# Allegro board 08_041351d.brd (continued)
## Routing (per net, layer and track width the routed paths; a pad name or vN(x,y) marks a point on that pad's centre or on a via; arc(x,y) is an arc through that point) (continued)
DDR3_DQ14: length 33
  TOP w0.197: U1.H1 v1(31.54,38.59)
  L12_SIGNAL w0.14: v1(48.83,18.77) 48.54,19.05 45.5,19.05 45.34,19.2 44.68,19.2 44.23,19.65 43.76,19.65 43.7,19.72 43.59,19.72 43.38,19.93 43.3,20 42.72,20 42.27,20.46 42.23,20.46 40.35,22.34 39.8,22.34 39.43,22.71 39.43,23.26 39.04,23.65 39.04,26.65 38.67,27.03 36.99,27.03 36.77,27.24 36.77,27.52 36.47,27.83 36.19,27.83 35.97,28.04 35.97,28.32 35.67,28.63 35.39,28.63 35.17,28.84 35.17,29.12 34.87,29.43 34.59,29.43 34.37,29.64 34.37,29.79 33.14,31.03 32.99,31.03 32.77,31.24 32.77,36.26 32.49,36.55 32.26,36.55 31.93,36.88 31.93,38.19 v1(31.54,38.59)
  BOTTOM w0.197: v1(48.83,18.77) U2.B8
DDR3_DQ15: length 33.1
  TOP w0.197: U1.J1 v1(30.74,38.59)
  L12_SIGNAL w0.14: v1(44.03,17.97) 44.03,17.41 43.74,17.13 41.84,17.13 37.14,21.83 36.63,21.83 36.23,22.23 36.19,22.23 35.9,22.52 35.9,24.39 35.66,24.63 35.39,24.63 35.17,24.84 35.17,25.12 34.86,25.43 34.59,25.43 34.37,25.64 34.37,25.92 34.06,26.23 33.79,26.23 33.57,26.44 33.57,26.72 33.26,27.03 32.99,27.03 32.77,27.24 32.77,27.52 32.46,27.83 32.19,27.83 31.97,28.04 31.97,28.32 31.66,28.63 31.39,28.63 31.17,28.84 31.17,29.12 30.86,29.43 30.59,29.43 30.37,29.64 30.37,30.13 30.03,30.48 30.03,30.59 29.9,30.72 29.64,30.72 29.52,30.84 29.52,38.02 29.64,38.15 30.01,38.15 30.45,38.59 v1(30.74,38.59)
  BOTTOM w0.197: U2.A3 v1(44.03,17.97)
DDR3_DQ16: length 30.3
  TOP w0.197: U1.P1 v1(25.94,38.59)
  L15_SIGNAL w0.14: v1(25.94,38.59) 25.94,39.83 26.21,40.11 30.28,40.11 30.66,40.49 39.55,40.49 39.93,40.88 41.45,40.88 41.71,40.62 41.71,40.24 41.58,40.11 39.65,40.11 39.42,39.89 39.42,39.57 39.65,39.35 41.45,39.35 41.58,39.22 41.58,38.97 41.45,38.84 40.44,38.84 40.31,38.72 40.31,38.21 40.53,37.99 41.98,37.99 42.28,38.29 42.58,38.29 42.87,37.99 v1(44.03,37.99)
  BOTTOM w0.197: U3.E3 44.09,37.99 v1(44.03,37.99)
DDR3_DQ17: length 30.2
  TOP w0.197: U1.P3 v1(25.94,36.99)
  L4_SIGNAL w0.14: v1(25.94,36.99) 25.94,37.04 26.34,37.45 26.34,39.61 26.99,40.25 28.11,40.25 28.37,39.99 30.91,39.99 31.93,38.97 35.1,38.97 35.24,39.11 35.24,39.59 35.38,39.73 35.66,39.73 35.8,39.59 35.8,39.11 35.94,38.97 36.22,38.97 36.36,39.11 36.36,39.73 36.49,39.86 36.79,39.86 36.92,39.73 36.92,39.11 37.06,38.97 39.8,38.97 41.33,37.45 44.25,37.45 44.5,37.7 46.93,37.7 v1(48.03,38.79)
  BOTTOM w0.197: U3.F7 47.96,38.79 v1(48.03,38.79)
DDR3_DQ18: length 30.4
  TOP w0.197: U1.R3 v1(25.14,36.99)
  L4_SIGNAL w0.14: v1(25.14,36.99) 25.14,37 25.57,37.44 25.57,39.85 26.34,40.62 28.12,40.62 28.37,40.88 28.37,43.29 28.63,43.54 30.28,43.54 30.53,43.29 30.53,40.88 30.79,40.62 32.62,40.62 32.76,40.48 32.76,40.13 32.9,39.99 33.18,39.99 33.32,40.13 33.32,40.48 33.46,40.62 33.73,40.62 33.87,40.48 33.87,40.13 34.01,39.99 34.29,39.99 34.43,40.13 34.43,40.48 34.57,40.62 39.04,40.62 41.07,38.59 42.06,38.59 42.28,38.37 42.58,38.37 42.8,38.59 43.09,38.59 v1(43.23,38.73)
  BOTTOM w0.197: U3.F2 v1(43.23,38.73)
DDR3_DQ19: length 30.3
  TOP w0.197: U1.R1 v1(25.14,38.59)
  L15_SIGNAL w0.14: v1(25.14,38.59) 25.14,40.3 25.71,40.88 39.17,40.88 39.55,41.26 41.84,41.26 42.09,41 42.09,40.5 42.06,40.48 42.06,39.37 42.34,39.09 44.25,39.09 45.78,40.62 47.17,40.62 47.42,40.37 47.42,40.2 v1(48.83,38.79)
  BOTTOM w0.197: U3.F8 48.76,38.79 v1(48.83,38.79)
DDR3_DQ20: length 30.3
  TOP w0.197: U1.T4 v1(24.34,36.19)
  L16_SIGNAL w0.14: v1(24.34,36.19) 23.9,36.63 22.89,36.63 22.6,36.63 22.3,36.32 22.3,35.29 22.56,35.03 24.56,35.03 24.77,35.24 24.77,35.54 24.99,35.75 25.28,35.75 25.57,36.04 25.57,37.94 25.86,38.23 26.09,38.23 26.37,38.52 26.37,38.74 26.59,38.95 26.7,38.95 27.74,39.99 30.28,39.99 30.79,40.49 40.57,40.49 40.82,40.75 43.61,40.75 v1(44.03,40.33)
  BOTTOM w0.197: U3.H3 v1(44.03,40.33)
DDR3_DQ21: length 30.4
  TOP w0.197: U1.U4 23.93,35.79 v1(23.53,36.19)
  L13_SIGNAL w0.14: v1(23.53,36.19) 23.93,36.59 23.93,38.59 23.97,38.63 23.97,38.74 26,40.76 26.36,40.76 26.37,40.77 28.12,40.77 28.34,40.99 30.42,40.99 30.63,40.77 36.47,40.77 36.5,40.75 39.68,40.75 40.31,40.11 42.13,40.11 42.28,39.97 44.18,39.97 44.32,40.11 45.9,40.11 46.15,39.86 48.19,39.86 48.66,40.33 v1(48.83,40.33)
  BOTTOM w0.197: U3.H8 v1(48.83,40.33)
DDR3_DQ22: length 30.3
  TOP w0.197: U1.U2 23.93,37.39 v1(23.53,37.79)
  L15_SIGNAL w0.14: v1(43.23,39.53) 42.85,39.9 42.85,41.13 42.34,41.64 39.3,41.64 38.91,41.26 22.79,41.26 20.63,39.1 20.63,38.35 20.75,38.23 20.99,38.23 21.01,38.21 23.11,38.21 v1(23.53,37.79)
  BOTTOM w0.197: U3.G2 v1(43.23,39.53)
DDR3_DQ23: length 30.3
  TOP w0.197: U1.U3 23.93,36.59 v1(23.53,36.99)
  L13_SIGNAL w0.14: v1(46.92,40.25) 46.55,40.62 44.76,40.62 44.12,41.26 30.03,41.26 29.91,41.38 26.6,41.38 26.48,41.26 23.42,41.26 22.79,40.62 22.79,39.35 23.17,38.97 23.17,37.35 v1(23.53,36.99)
  BOTTOM w0.197: U3.H7 47.15,40.25 v1(46.92,40.25)
DDR3_DQ24: length 30.5
  TOP w0.197: U1.V1 v1(22.74,38.59)
  L7_SIGNAL w0.14: v1(22.74,38.59) 23.12,38.97 23.55,38.97 24.07,39.49 25.47,39.49 25.49,39.5 28.17,39.5 28.19,39.49 34.89,39.49 35.03,39.63 35.03,39.97 35.17,40.11 35.44,40.11 35.58,39.97 35.58,39.63 35.72,39.49 36,39.49 36.14,39.63 36.14,39.97 36.28,40.11 36.56,40.11 36.7,39.97 36.7,39.63 36.84,39.49 38.77,39.49 38.78,39.48 40.44,39.48 41.96,37.95 41.96,37.82 43.08,36.7 43.34,36.7 43.36,36.68 43.87,36.68 43.88,36.69 45.78,36.69 46.79,37.7 47.52,37.7 v1(48.03,37.19)
  BOTTOM w0.197: v1(48.03,37.19) 47.96,37.19 U3.D7
DDR3_DQ25: length 30.5
  TOP w0.197: U1.Y3 v1(21.14,36.99)
  L13_SIGNAL w0.14: v1(44.03,36.33) 43.66,36.69 42.84,36.69 42.47,37.07 39.29,37.07 37.76,38.59 37.76,39.11 36.36,40.51 30.8,40.51 30.29,40 28.61,40 28.59,40.01 25.73,40.01 24.7,38.98 24.7,36.04 24.48,35.83 21.79,35.83 21.57,36.04 21.57,36.26 21.14,36.7 v1(21.14,36.99)
  BOTTOM w0.197: U3.C3 v1(44.03,36.33)
DDR3_DQ26: length 30.6
  TOP w0.197: U1.W1 v1(21.94,38.59)
  L7_SIGNAL w0.14: v1(48.83,36.27) 48.45,35.89 47.88,35.89 47.78,35.8 45.17,35.8 45.01,35.95 43.09,35.95 42.86,36.18 42.86,36.42 42.47,36.81 41.71,36.81 39.31,39.21 38.67,39.21 38.66,39.22 28.08,39.22 28.06,39.24 25.6,39.24 25.58,39.22 24.46,39.22 23.97,38.74 23.97,38.52 23.66,38.21 22.4,38.21 22.02,38.59 v1(21.94,38.59)
  BOTTOM w0.197: v1(48.83,36.27) 48.83,36.33 U3.C8
DDR3_DQ27: length 30.4
  TOP w0.197: U1.Y4 v1(21.14,36.19)
  L13_SIGNAL w0.14: v1(21.14,36.19) 21.14,35.9 21.57,35.46 21.57,35.24 21.79,35.03 25.32,35.03 25.57,35.28 25.57,38.97 26.35,39.75 28.48,39.75 28.5,39.73 30.53,39.73 31.04,40.24 35.99,40.24 37.28,38.95 37.29,38.95 37.5,38.74 37.5,38.48 39.3,36.68 41.45,36.68 42.22,35.92 42.82,35.92 v1(43.23,36.33)
  BOTTOM w0.197: U3.C2 v1(43.23,36.33)
DDR3_DQ28: length 30.5
  TOP w0.197: U1.Y2 v1(21.14,37.79)
  L15_SIGNAL w0.14: v1(48.03,34.73) 46.96,35.8 44.5,35.8 44.34,35.95 42.29,35.95 39.57,36.93 39.55,36.94 37.51,38.21 30.66,38.21 30.6,38.15 30.59,38.15 30.37,37.94 30.3,37.64 30.09,37.43 30.01,37.43 27.46,37.43 27.17,37.14 27.17,36.92 26.88,36.63 24.99,36.63 23.38,36.63 23.1,36.91 23.1,37.14 22.89,37.35 21.9,37.35 v1(21.14,37.79)
  BOTTOM w0.197: U3.A7 v1(48.03,34.73)
DDR3_DQ29: length 30.5
  TOP w0.197: U1.W3 v1(21.94,36.99)
  L15_SIGNAL w0.14: v1(43.23,34.67) 43.75,34.14 44.53,34.14 44.76,33.92 44.76,33.61 44.53,33.38 41.96,33.38 41.14,34.21 40.13,34.21 40.08,34.25 39.82,34.25 37.52,36.56 30.59,36.56 30.3,36.26 30.3,36.04 30.09,35.83 28.28,35.83 28.2,35.75 28.19,35.75 27.97,35.54 27.97,35.32 27.69,35.03 22.59,35.03 22.3,35.32 22.3,35.54 22.01,35.83 21.79,35.83 21.57,36.04 21.57,36.63 v1(21.94,36.99)
  BOTTOM w0.197: v1(43.23,34.67) 43.23,34.73 U3.A2
DDR3_DQ30: length 30.1
  TOP w0.197: U1.V2 v1(22.74,37.79)
  L15_SIGNAL w0.14: v1(48.83,35.53) 48.39,35.97 48.39,36.42 48.11,36.69 42.84,36.69 42.34,37.19 39.93,37.19 38.03,39.1 30.78,39.1 30.63,38.95 30.58,38.95 30.37,38.74 30.37,38.44 30.09,38.15 27.39,38.15 27.17,37.94 27.17,37.72 26.88,37.43 23.19,37.43 23,37.62 22.91,37.62 v1(22.74,37.79)
  BOTTOM w0.197: U3.B8 v1(48.83,35.53)
DDR3_DQ31: length 30.5
  TOP w0.197: U1.V3 v1(22.74,36.99)
  L15_SIGNAL w0.14: v1(44.03,34.67) 44.04,34.65 45.01,34.65 45.14,34.53 45.77,34.53 45.79,34.55 45.8,34.55 46.01,34.76 46.01,35.06 45.8,35.27 45.79,35.27 45.77,35.29 44.88,35.29 44.76,35.16 40.31,35.16 40.08,35.39 39.57,35.39 37.61,37.35 30.59,37.35 30.37,37.14 30.37,36.91 30.02,36.56 27.61,36.56 27.6,36.55 27.39,36.55 27.17,36.34 27.17,36.12 26.88,35.83 22.59,35.83 22.3,36.12 22.3,36.55 v1(22.74,36.99)
  BOTTOM w0.197: U3.A3 44.03,34.73 v1(44.03,34.67)
DDR3_DQS0_N: length 30.4
  TOP w0.152: v1(36.34,37.79) U1.B2
  L12_SIGNAL w0.13: v1(44.83,22.77) 44.8,22.77 44.63,22.59 44.63,22.33 44.5,22.21 44.35,22.21 44.25,22.31 44.25,24.47 43.72,25 42.09,25 41.45,25.64 41.45,29.95 39.3,32.11 39.3,33.89 39.04,34.14 38.15,34.14 37.9,33.89 37.9,30.91 37.39,30.4 36.99,30.4 36.61,30.78 36.56,30.78 36.47,30.88 36.47,30.97 36.6,31.1 36.63,31.1 36.76,31.22 36.76,37.32 36.34,37.74 v1(36.34,37.79)
  BOTTOM w0.152: U2.G3 v1(44.83,22.77)
DDR3_DQS0_P: length 30.4
  TOP w0.152: U1.C2 v1(35.54,37.79)
  L12_SIGNAL w0.13: v1(44.83,21.97) 44.81,21.95 44.25,21.95 43.99,22.21 43.99,24.37 43.62,24.74 41.98,24.74 41.2,25.53 41.2,29.85 39.04,32.01 39.04,33.78 38.93,33.89 38.26,33.89 38.15,33.78 38.15,30.8 37.5,30.14 36.88,30.14 36.5,30.53 36.45,30.53 35.98,31 35.98,37.35 v1(35.54,37.79)
  BOTTOM w0.152: U2.F3 v1(44.83,21.97)
DDR3_DQS1_N: length 32.8
  TOP w0.152: U1.F2 v1(33.14,37.79)
  L6_SIGNAL w0.13: v1(47.23,19.59) 47.4,19.42 47.4,19.24 47.06,18.9 46.92,18.9 46.79,19.03 46.53,19.03 46.41,18.9 43.59,18.9 43.37,19.12 42.94,19.12 42.9,19.16 41.71,19.16 40.54,20.32 40.54,20.56 40.18,20.91 39.95,20.91 37.9,22.97 37.9,29.05 37.75,29.2 37.75,29.24 37.46,29.53 37.46,29.61 37.49,29.64 37.49,29.94 37.28,30.14 36.99,30.14 36.96,30.12 36.87,30.12 36.59,30.4 36.54,30.4 36.35,30.59 34.32,30.59 34.09,30.82 34.09,30.97 34.34,31.22 34.34,35.57 34.08,35.83 33.79,35.83 33.53,36.08 33.53,38.08 33.41,38.21 33.23,38.21 33.14,38.12 v1(33.14,37.79)
  BOTTOM w0.152: U2.B7 47.23,19.57 v1(47.23,19.59)
DDR3_DQS1_P: length 32.8
  TOP w0.152: U1.G2 v1(32.34,37.79)
  L6_SIGNAL w0.13: v1(48.03,19.59) 47.68,19.24 47.68,19.16 47.17,18.65 43.61,18.65 43.37,18.41 42.28,18.41 42.07,18.62 42.07,18.79 41.96,18.9 41.6,18.9 40.29,20.22 40.29,20.45 40.08,20.66 39.85,20.66 37.64,22.86 37.64,23.07 37.64,28.94 37.49,29.09 37.49,29.14 37.28,29.34 37.24,29.34 37.15,29.43 36.99,29.43 36.78,29.64 36.78,29.8 36.69,29.89 36.69,29.94 36.48,30.14 36.44,30.14 36.25,30.33 34.22,30.33 33.83,30.72 33.83,30.97 33.58,31.22 33.58,35.68 33.42,35.83 32.99,35.83 32.78,36.04 32.78,37.35 v1(32.34,37.79)
  BOTTOM w0.152: U2.C7 48,19.59 v1(48.03,19.59)
DDR3_DQS2_N: length 30.5
  TOP w0.152: U1.T2 v1(24.34,37.79)
  L4_SIGNAL w0.13: v1(44.03,39.53) 43.73,39.53 43.37,39.89 42.28,39.89 42.07,39.68 41.38,39.68 39.8,41.26 31.45,41.26 31.19,41.51 31.19,44.03 30.66,44.56 28.12,44.56 27.71,44.15 27.71,41.62 27.51,41.41 27.36,41.26 25.6,41.26 24.18,39.84 24.18,38.97 23.93,38.72 23.93,38.21 24.34,37.8 v1(24.34,37.79)
  BOTTOM w0.152: U3.G3 v1(44.03,39.53)
DDR3_DQS2_P: length 30.5
  TOP w0.152: U1.R2 v1(25.14,37.79)
  L4_SIGNAL w0.13: v1(25.14,37.79) 25.1,37.83 24.82,37.83 24.69,37.95 24.69,38.74 24.44,38.99 24.44,39.73 25.71,41 27.46,41 27.61,41.15 27.97,41.51 27.97,44.05 28.23,44.3 30.55,44.3 30.94,43.92 30.94,41.41 31.34,41 39.69,41 41.28,39.42 41.77,39.42 42.01,39.17 43.92,39.17 43.99,39.1 43.99,38.76 v1(44.03,38.73)
  BOTTOM w0.152: U3.F3 v1(44.03,38.73)
DDR3_DQS3_N: length 30.3
  TOP w0.152: U1.W4 v1(21.94,36.19)
  L4_SIGNAL w0.13: v1(48.03,35.53) 48.03,35.67 47.77,35.92 47.68,35.92 47.42,35.67 47.17,35.67 46.92,35.92 46.79,35.92 46.28,35.41 43.74,35.41 43.5,35.17 42.28,35.17 42.04,35.41 41.58,35.41 40.31,36.68 38.15,36.68 37.26,35.8 29.77,35.8 29.65,35.92 28.88,35.92 28.76,35.8 24.06,35.8 23.88,35.62 23.88,35.24 23.68,35.03 23.38,35.03 23.17,35.25 23.17,35.6 22.97,35.8 22.28,35.8 21.94,36.14 v1(21.94,36.19)
  BOTTOM w0.152: U3.B7 v1(48.03,35.53)
DDR3_DQS3_P: length 30.3
  TOP w0.152: U1.W5 v1(21.94,35.39)
  L4_SIGNAL w0.13: v1(21.94,35.39) 21.94,35.68 21.58,36.04 21.58,36.34 21.79,36.54 22.14,36.54 22.15,36.56 28.5,36.56 28.88,36.18 29.39,36.18 29.77,36.56 37.66,36.56 38.05,36.94 40.42,36.94 41.69,35.67 42.06,35.67 42.28,35.89 42.43,35.89 42.53,35.98 43.07,35.98 43.08,35.97 43.49,35.97 43.79,35.67 46.17,35.67 46.68,36.18 47.94,36.18 v1(48.03,36.27)
  BOTTOM w0.152: U3.C7 48.03,36.33 v1(48.03,36.27)
DDR3_ODT: length 55.5
  TOP w0.197: U1.N5 v1(26.74,35.39) ; v1(42.43,42.73) 42.1,42.4 41.01,42.4 R162.1
  L12_SIGNAL w0.14: v1(42.43,42.73) 42.43,41.05 42.85,40.62 42.85,34.27 44.5,32.62 44.5,29.19 44.12,28.81 43.87,28.81 43.59,28.53 43.59,26.62 43.3,26.33 42.79,26.33 v1(42.43,25.97)
  L16_SIGNAL w0.14: v1(26.74,35.39) 26.75,35.39 27.11,35.03 28.75,35.03 29.14,35.41 29.14,37.7 29.64,38.21 39.8,38.21 41.58,36.43 41.58,33.89 43.61,31.86 43.61,28.18 43.38,27.94 43.08,27.94 43.08,27.94 42.58,27.94 42.58,27.94 42.2,27.94 41.68,28.46 41.48,28.46 41.33,28.3 41.33,27.88 42.43,26.78 v1(42.43,25.97)
  BOTTOM w0.197: U2.K1 v1(42.43,25.97) ; U3.K1 v1(42.43,42.73)
DDR3_RAS#: length 53
  TOP w0.197: v1(44.03,41.93) 44.37,42.27 45.33,42.27 R156.1 ; U1.P4 v1(25.94,36.19)
  L12_SIGNAL w0.14: v1(44.03,41.93) 45.26,40.69 45.26,29.56 45.4,29.42 45.63,29.42 45.77,29.28 45.77,29 45.63,28.86 45.4,28.86 45.26,28.72 45.26,28.44 45.4,28.3 45.63,28.3 45.77,28.16 45.77,27.88 45.63,27.74 45.4,27.74 45.26,27.6 45.26,25.64 44.83,25.2 v1(44.83,25.17)
  L16_SIGNAL w0.14: v1(44.83,25.17) 44.39,25.85 44.39,31.86 42.79,34.47 42.79,34.82 42.58,35.03 42.48,35.03 42.34,35.17 42.28,35.17 42.06,35.38 42.06,35.44 41.96,35.54 41.96,36.56 40.06,38.46 37.39,38.97 29.77,38.97 28.57,38.15 28.19,38.15 27.97,37.94 27.97,37.68 27.64,37.35 27.39,37.35 27.17,37.14 27.17,36.92 26.89,36.63 26.37,36.63 v1(25.94,36.19)
  BOTTOM w0.197: U3.J3 v1(44.03,41.93) ; U2.J3 v1(44.83,25.17)
DDR3_RST#: length 52.3
  TOP w0.197: v1(43.23,47.53) 43.41,47.53 43.99,48.11 43.99,48.37 43.85,48.51 43.56,48.51 R133.1 ; v1(36.34,36.19) U1.B4
  L12_SIGNAL w0.14: v1(43.23,30.77) 43.19,30.8 43.19,31.14 42.89,31.44 42.26,31.44 41.33,32.37 41.33,44.94 42.06,45.68 42.06,46.08 42.28,46.29 42.68,46.29 42.85,46.46 42.85,47.15 v1(43.23,47.53)
  L16_SIGNAL w0.14: v1(36.34,36.19) 35.98,36.54 35.69,36.54 35.69,36.55 29.78,36.55 29.52,36.81 29.52,37.19 29.75,37.43 37.29,37.43 37.43,37.57 39.93,37.57 40.95,36.56 40.95,34.14 40.82,34.02 40.44,34.02 40.31,33.89 40.31,32.33 40.44,32.2 40.82,32.2 40.95,32.33 40.95,33.26 41.07,33.38 41.58,33.38 41.71,33.26 41.71,32.28 v1(43.23,30.77)
  BOTTOM w0.197: v1(43.23,47.53) U3.T2 ; U2.T2 v1(43.23,30.77)
DDR3_WE#: length 51
  TOP w0.197: U1.M5 v1(27.54,35.39) ; v1(44.03,43.53) 44.29,43.8 45.33,43.8 R155.1
  L6_SIGNAL w0.14: v1(44.03,43.53) 44.03,43.32 43.61,42.91 43.61,35.92 44.31,35.22 44.82,35.22 44.95,35.1 44.95,34.59 46.03,33.51 46.03,27.97 v1(44.83,26.77)
  L7_SIGNAL w0.14: v1(27.54,35.39) 27.5,35.42 27.24,35.42 27.14,35.32 27.14,35.13 27.3,34.97 27.67,34.97 27.9,34.74 27.9,34.49 28.24,34.15 28.49,34.15 28.7,33.94 28.7,33.52 28.96,33.25 28.96,32.83 29.24,32.55 30.09,32.55 30.3,32.34 30.3,32.09 30.64,31.75 30.91,31.75 31.04,31.62 31.04,31.59 31.1,31.54 31.1,31.24 31.04,31.18 31.04,30.84 31.17,30.72 37.9,30.72 38.03,30.59 38.03,29.82 39.98,27.87 41,27.87 41.33,27.54 41.33,26.92 41.58,26.66 42.61,26.66 42.98,27.03 42.98,27.03 43.11,27.16 46.92,27.16 47.04,27.03 47.04,26.89 46.92,26.77 v1(44.83,26.77)
  BOTTOM w0.197: U3.L3 v1(44.03,43.53) ; U2.L3 v1(44.83,26.77)
DX_0_N: length 54.8
  TOP w0.089: U1.M10 v1(27.54,31.39)
  L4_SIGNAL w0.089: v1(70.28,48.93) 70.28,47.86 69.08,46.65 61.24,46.65 52.12,37.53 52.12,35.31 49.43,32.62 39.53,32.62 38.96,32.05 37.52,32.05 37.2,31.73 27.9,31.73 27.56,31.39 v1(27.54,31.39)
  BOTTOM w0.089: v1(70.28,48.93) 70.04,49.18 70.04,49.94 70.33,50.23 JX1.100
DX_0_P: length 54.8
  TOP w0.089: U1.M9 v1(27.54,32.19)
  L4_SIGNAL w0.089: v1(27.54,32.19) 27.54,32.47 27.66,32.6 37.23,32.6 37.52,32.3 38.85,32.3 39.42,32.87 49.33,32.87 51.87,35.41 51.87,37.64 61.14,46.91 68.97,46.91 70.03,47.97 70.03,48.62 69.91,48.74 69.77,48.74 v1(69.57,48.93)
  BOTTOM w0.089: JX1.98 69.53,50.23 69.82,49.94 69.82,49.18 v1(69.57,48.93)
ETH_MD1_N: length 30.1
  L12_SIGNAL w0.089: v1(16.31,11.92) 16.5,12.11 16.5,14.21 16.19,14.51 16.13,14.51 15.29,15.35 15.29,17.13 15.42,17.25 15.42,23.5 10.59,28.32 10.59,29.21 10.23,29.57 8.96,29.57 8.31,30.23 8.31,31.46 8.96,32.11 v1(9.58,32.11)
  BOTTOM w0.089: v1(16.31,11.92) 16.54,11.69 16.54,11.51 16.73,11.32 16.73,10.31 16.98,10.05 17.16,10.05 17.37,9.84 U10.27 ; JX3.53 8.88,32.17 9.2,31.86 9.32,31.86 v1(9.58,32.11)
ETH_MD1_P: length 30.1
  L12_SIGNAL w0.089: v1(9.58,31.48) 9.32,31.73 9.32,31.77 9.23,31.86 9.07,31.86 8.56,31.35 8.56,30.33 9.07,29.83 10.34,29.83 10.85,29.32 10.85,28.43 15.67,23.6 15.67,17.15 15.55,17.02 15.55,15.45 16.23,14.77 16.49,14.77 16.56,14.84 16.69,14.84 17.07,14.46 17.07,14.14 16.75,13.82 16.75,13.51 16.94,13.32 16.94,12.87 16.75,12.68 16.75,12.11 v1(16.94,11.92)
  BOTTOM w0.089: v1(9.58,31.48) 9.41,31.64 9.2,31.64 8.93,31.37 JX3.51 ; U10.28 17.4,10.34 17.32,10.27 17.07,10.27 16.94,10.4 16.94,11.41 16.75,11.6 16.75,11.73 v1(16.94,11.92)
ETH_MD2_N: length 30.7
  L6_SIGNAL w0.089: v1(14.02,32.11) 15.61,32.11 16.31,31.41 16.31,23.58 18.59,21.3 18.59,14.23 17.83,13.47 17.83,12.43 19.19,11.07 v1(19.19,10.14)
  BOTTOM w0.089: v1(14.02,32.11) 13.79,31.88 13.56,31.88 13.26,32.17 JX3.54 ; v1(19.19,10.14) 18.98,9.93 18.98,9.63 18.68,9.34 18.68,8.1 18.43,7.84 U10.23
ETH_MD2_P: length 30.7
  L6_SIGNAL w0.089: v1(18.47,10.14) 18.66,10.33 18.81,10.33 18.94,10.46 18.94,10.96 17.58,12.32 17.58,13.57 18.34,14.33 18.34,21.19 16.05,23.48 16.05,31.31 15.5,31.86 14.34,31.86 14.21,31.73 14.21,31.59 v1(14.02,31.4)
  BOTTOM w0.089: v1(14.02,31.4) 13.76,31.66 13.57,31.66 13.28,31.37 JX3.52 ; v1(18.47,10.14) 18.76,9.9 18.76,9.72 18.47,9.43 18.47,8.19 18.34,8.06 18.2,8.06 17.92,8.34 U10.24
ETH_MD3_N: length 42.9
  L12_SIGNAL w0.089: v1(16.31,8.49) 16.31,6.59 16.56,6.33 17.32,6.33 17.83,6.84 17.83,13.19 18.47,13.82 18.47,21.57 16.69,23.35 16.69,26.65 12.88,30.46 12.88,32.47 11.33,34.02 6.28,34.02 v1(6.02,34.27)
  BOTTOM w0.089: JP2.1 5.46,34.53 5.72,34.27 v1(6.02,34.27) ; U10.21 17.3,6.84 17.14,7 16.98,7 16.6,7.39 16.6,8.2 v1(16.31,8.49)
ETH_MD3_P: length 42.9
  L12_SIGNAL w0.089: v1(16.82,8.49) 16.56,8.24 16.56,7.86 16.82,7.6 16.82,7.35 16.56,7.09 16.56,6.69 16.67,6.59 17.22,6.59 17.58,6.94 17.58,13.29 18.21,13.93 18.21,21.47 16.44,23.24 16.44,26.55 12.63,30.36 12.63,32.37 11.23,33.76 7.93,33.76 7.67,33.51 7.42,33.51 7.16,33.76 7.04,33.76 6.78,33.51 6.66,33.51 6.4,33.76 6.15,33.76 5.89,33.51 5.89,33.38 6.02,33.26 v1(6.02,33)
  BOTTOM w0.089: v1(6.02,33) 5.64,33 5.46,32.82 JP1.1 ; U10.22 17.32,7.34 17.2,7.22 17.07,7.22 16.82,7.48 v1(16.82,8.49)
ETH_MD4_N: length 35.5
  L13_SIGNAL w0.089: v1(12.88,8.24) 13.07,8.43 13.07,32.41 13.54,32.87 14.15,32.87 14.68,32.34 15.02,32.34 15.11,32.44 15.11,32.6 v1(14.83,32.88)
  BOTTOM w0.089: JP4.1 14.84,32.87 v1(14.83,32.88) ; U10.17 17.27,4.84 17.14,4.97 16.47,4.97 16.35,5.1 13.71,5.1 13.13,5.68 13.13,7.99 v1(12.88,8.24)
ETH_MD4_P: length 35.5
  L13_SIGNAL w0.089: v1(14.78,30.72) 15.04,30.97 15.04,31.99 14.93,32.09 14.57,32.09 14.04,32.62 13.64,32.62 13.32,32.3 13.32,8.43 v1(13.51,8.24)
  BOTTOM w0.089: v1(13.51,8.24) 13.34,8.07 13.34,5.77 13.8,5.32 16.44,5.32 16.56,5.19 17.2,5.19 17.35,5.34 U10.18 ; JP3.1 15.42,30.72 v1(14.78,30.72)
ETH_PHY_LED0: length 21.7
  TOP w0.14: R18.2 v2(3.86,47.86)
  L16_SIGNAL w0.095: v2(3.86,47.86) 3.86,46.34 5.26,44.94 5.26,30.84 6.33,29.77 v1(6.84,29.77)
  BOTTOM w0.14: v1(6.84,29.77) JX3.47
ETH_PHY_LED1: length 46.7
  TOP w0.14: R17.2 v1(41.07,12.3)
  L4_SIGNAL w0.095: v1(41.07,12.3) 39.87,11.09 37.71,11.09 37.14,11.67 37.14,12.3 36.5,12.94 36.5,14.71 35.1,16.11 33.71,16.11 33.26,16.55 32.06,16.55 31.23,15.73 26.21,15.73 25.26,16.68 21.58,16.68 21.07,17.19 15.48,17.19 13.9,18.78 13.9,29.45 14.09,29.64 v1(14.09,30.02)
  BOTTOM w0.14: JX3.48 13.84,29.77 v1(14.09,30.02)
FB0: length 6.4
  TOP w0.14: U18.4 25.16,7.31 R29.2 24.44,9.38 22.79,9.38 21.86,10.31 R48.1
FB_1P8V: length 3.8
  TOP w0.14: v1(63.49,2.65) 63.82,2.98 U4.32
  BOTTOM w0.14: R45.1 R39.2 64.44,3.03 63.87,3.03 v1(63.49,2.65)
FB_1P35V: length 5.8
  TOP w0.305: R34.1 73.03,1.56 72.75,1.56 ; 72.75,1.56 71.12,1.56 69.7,2.98 U4.9 ; 72.75,1.56 R35.1
FPGA_DONE: length 33.7
  TOP w0.127: U1.R11 v1(25.14,29.79)
  TOP w0.14: R172.2 35.36,51.42 34.45,52.33 v1(33.58,52.33)
  L6_SIGNAL w0.095: v1(25.2,44.69) 25.2,41.26 24.8,40.85 24.8,30.23 25.14,29.89 v1(25.14,29.79)
  L7_SIGNAL w0.095: v1(25.2,44.69) 25.2,46.08 25.71,46.59 26.21,46.59 27.61,47.99 31.29,47.99 32.31,49 32.31,51.06 v1(33.58,52.33)
  BOTTOM w0.14: JX1.8 33.53,52.25 33.58,52.31 v1(33.58,52.33)
FPGA_VBATT: length 110.9
  TOP w0.127: v1(33.14,29.79) U1.F11
  TOP w0.14: R9.2 24.18,48.11 24.56,48.11 25.45,47.23 v1(26.09,47.23)
  L6_SIGNAL w0.102: v1(26.09,47.23) 24.69,48.62 24.69,49.64 24.44,49.89 24.44,52.43 22.5,54.37 22.5,56.97 23.48,57.96 29.45,57.96 30.02,58.53 33.2,58.53 33.53,58.2 v1(33.53,57.64) 34.47,57.64 35.1,58.27 43.64,58.27 45.67,60.31 55.66,60.31 57.08,58.88 71.2,58.88 78.29,51.79 78.29,43.67 v1(78.03,43.41)
  BOTTOM w0.102: v1(33.14,29.79) 33.14,29.89 32.69,30.33 30.79,30.33 30.28,30.84 30.28,35.65 30.08,35.85 29.79,35.85 29.59,36.05 29.59,36.48 29.14,36.94 29.14,38.72 28.5,39.35 26.34,39.35 25.45,40.24 25.45,43.92 25.58,44.05 25.58,46.08 26.09,46.59 v1(26.09,47.23)
  BOTTOM w0.14: JX1.7 v1(33.53,57.64)
  BOTTOM w0.254: U24.20 78.03,43.83 v1(78.03,43.41)
GPO0: length 42.9
  TOP w0.127: U17.B7 62,29.69 v1(62,29.69)
  L16_SIGNAL w0.095: v1(62,29.69) 64.49,29.69 65.69,30.89 69.57,30.89 70.28,31.6 70.28,36.94 75.36,42.02 75.36,43.54 74.73,44.18 74.73,46.46 79.43,51.16 80.49,51.16 81.09,50.57 v1(87.26,50.57)
  BOTTOM w0.14: JX4.1 v1(87.26,50.57)
GPO1: length 35.8
  TOP w0.127: U17.B6 v1(61.2,28.89)
  L16_SIGNAL w0.095: v1(61.2,28.89) U17.B6 64.75,29.29 65.54,30.08 69.58,30.08 70.73,31.22 70.73,36.87 77.78,43.92 77.78,48.29 v1(80.06,50.57)
  BOTTOM w0.14: JX4.2 v1(80.06,50.57)
GPO2: length 48
  TOP w0.127: U17.B5 v1(61.2,28.09)
  L16_SIGNAL w0.095: v1(87.3,49.77) 87.31,49.77 87.81,50.27 87.81,50.81 87.5,51.11 81.23,51.11 80.8,51.54 79.3,51.54 74.41,46.65 74.41,43.99 74.98,43.42 74.98,42.15 69.84,37 69.84,31.99 69.53,31.68 65.66,31.68 64.82,30.84 61.52,30.84 60.76,30.08 60.76,28.56 61.2,28.12 v1(61.2,28.09)
  BOTTOM w0.14: JX4.3 v1(87.3,49.77)
GPO3: length 37.5
  TOP w0.127: U17.B4 v1(61.2,27.29)
  L16_SIGNAL w0.095: v1(80.06,49.77) 80.06,48.88 79.68,48.5 78.67,48.5 78.41,48.24 78.41,42.65 75.68,39.92 75.68,36.18 74.82,35.32 73.74,35.32 71.93,33.51 71.93,31.73 69.9,29.7 65.71,29.7 64.52,28.51 62.56,28.51 62.38,28.33 62.38,27.95 62.13,27.69 61.57,27.69 61.2,27.32 v1(61.2,27.29)
  BOTTOM w0.14: JX4.4 80.06,49.77 v1(80.06,49.77)
INIT_B_0_JX2_09: length 51.4
  TOP w0.14: U1.R10 v1(25.14,31.39) ; v1(35.36,46.34) 35.61,46.59 R168.2
  L6_SIGNAL w0.095: v1(32.69,14.97) 32.31,15.35 32.31,16.87 31.29,17.89 31.29,18.78 30.53,19.54 30.53,21.22 30.44,21.32 30.41,21.32 29.52,22.21 29.52,26.44 28.97,26.98 26.53,26.98 26.32,27.2 26.32,30.21 v1(25.14,31.39) 25.14,31.41 25.58,31.86 25.58,44.3 v1(25.96,44.69)
  L7_SIGNAL w0.095: v1(35.36,46.34) 34.34,45.32 33.71,45.32 33.33,45.7 28.12,45.7 27.1,44.69 v1(25.96,44.69)
  BOTTOM w0.14: JX2.9 34.33,12.57 32.69,14.21 v1(32.69,14.97)
IO_00_34_AD9364_CLKSEL: length 97.1
  TOP w0.127: U1.R19 v1(25.14,23.39)
  TOP w0.14: Q6.1 84.61,55.57 84.48,55.44 v1(82.6,55.44)
  L3_SIGNAL w0.095: v1(76.51,49.89) 76.51,50.78 78.41,52.69 79.85,52.69 v1(82.6,55.44)
  L4_SIGNAL w0.095: v1(25.14,23.39) 25.16,23.39 25.47,23.07 25.47,22.5 26.72,21.25 36.37,21.25 38.98,18.65 v1(39.68,18.65)
  L16_SIGNAL w0.095: v1(39.68,18.65) 40.18,19.16 45.42,19.16 45.5,19.07 47.99,19.07 48.44,19.52 48.44,19.79 49.47,20.83 49.77,20.83 50.18,21.23 50.18,46.86 49.97,47.07 49.97,47.95 50.6,48.58 64.1,48.58 65.08,47.61 69.98,47.61 71.25,48.88 73.2,48.88 74.22,49.89 v1(76.51,49.89)
  BOTTOM w0.14: R54.1 75.74,50.65 v1(76.51,49.89)
IO_00_35_AD9364_RST: length 46.7
  TOP w0.127: U1.G14 v1(32.34,27.39) ; U17.K5 v1(68.4,28.09)
  L4_SIGNAL w0.095: v1(32.34,27.39) 31.93,26.98 31.93,23.22 32.18,22.97 38.79,22.97 39.23,23.41 41.71,23.41 41.96,23.16 53.12,23.16 53.13,23.17 53.22,23.17 53.71,23.67 64,23.67 64.89,24.56 64.89,25.44 65.27,25.83 65.27,28.11 65.71,28.55 68,28.55 68.4,28.16 v1(68.4,28.09)
IO_25_34_JX4: length 67.9
  TOP w0.127: U1.T19 v1(24.34,23.39)
  L3_SIGNAL w0.095: v1(24.34,23.39) 24.74,22.98 24.74,20.52 27.94,17.32 41.43,17.32 41.91,16.83 54.5,16.83 55.68,18.02 61.14,18.02 v1(61.65,18.52)
  BOTTOM w0.14: JX4.64 80,25.77 79.71,25.48 79.71,21.57 79.07,20.94 71.68,20.94 70.41,19.67 65.77,19.67 64.63,18.52 v1(61.65,18.52)
IO_25_35_AD9364_CLKOUT: length 53.6
  TOP w0.127: U17.J6 v1(67.6,28.89) ; U1.J15 v1(30.74,26.59)
  L7_SIGNAL w0.095: v1(30.74,26.59) 30.47,26.59 30.02,26.14 29.64,26.14 29.39,25.89 29.39,24.9 29.69,24.59 30.81,24.59 31.17,24.24 31.17,21.83 32.82,20.17 34.6,20.17 35.36,19.41 36.76,19.41 39.04,17.13 40.06,17.13 41.24,18.3 49.77,18.3 49.8,18.27 54.28,18.27 55.36,19.35 55.36,20.11 59.74,24.49 64.95,24.49 65.58,25.13 66.09,25.13 66.41,25.44 66.41,28.3 66.6,28.49 67.2,28.49 v1(67.6,28.89)
IO_L01_34_JX4_N: length 81.4
  TOP w0.089: U1.T10 v1(24.34,31.39)
  L4_SIGNAL w0.089: v1(24.34,31.39) 24.76,30.96 41.46,30.96 42.16,31.67 51.07,31.67 60.15,40.75 65.22,40.75 71.38,46.91 90.14,46.91 90.67,46.38 90.67,44.58 88.73,42.64 v1(87.81,42.64)
  BOTTOM w0.089: v1(87.81,42.64) 87.59,42.86 86.99,42.86 86.7,42.57 JX4.21
IO_L01_34_JX4_P: length 81.3
  TOP w0.089: U1.T11 v1(24.34,29.79)
  L4_SIGNAL w0.089: v1(87.81,43.35) 88.27,42.89 88.62,42.89 90.41,44.69 90.41,46.27 90.03,46.65 71.49,46.65 65.33,40.49 60.25,40.49 51.17,31.41 42.27,31.41 41.56,30.71 24.71,30.71 24.34,30.33 v1(24.34,29.79)
  BOTTOM w0.089: JX4.19 86.7,43.37 86.99,43.08 87.54,43.08 v1(87.81,43.35)
IO_L01_35_RX_D0_N: length 56.2
  TOP w0.089: U17.K11 v1(68.4,33.69) ; U1.B20 v1(36.34,22.59)
  L6_SIGNAL w0.089: v1(68.4,33.69) 68.79,34.09 68.79,35.31 67.67,36.43 58.31,36.43 57.98,36.09 57.59,36.09 55.55,34.05 55.55,28.47 51.04,23.96 51.04,18.59 48.76,16.3 41.12,16.3 39.91,17.51 36.99,17.51 36.32,18.17 36.32,19.93 35.87,20.39 35.87,20.86 36.34,21.33 v1(36.34,22.59)
IO_L01_35_RX_D0_P: length 56.2
  TOP w0.089: U17.J12 v1(67.6,34.49) ; U1.C20 v1(35.54,22.59)
  L6_SIGNAL w0.089: v1(35.54,22.59) 35.81,22.32 35.99,22.32 36.08,22.23 36.08,21.43 35.61,20.97 35.61,20.29 36.07,19.83 36.07,18.07 36.88,17.25 39.8,17.25 41.01,16.05 48.86,16.05 51.3,18.48 51.3,23.86 55.81,28.37 55.81,33.95 57.7,35.84 58.08,35.84 58.42,36.18 67.57,36.18 68.54,35.2 68.54,34.95 68.42,34.83 67.93,34.83 v1(67.6,34.49)
IO_L02_34_JX4_N: length 89.9
  TOP w0.089: U1.U12 v1(23.54,28.99)
  L15_SIGNAL w0.089: v1(80.04,42.6) 80.22,42.79 80.22,42.93 80.35,43.06 80.67,43.06 81.06,42.67 81.06,42.13 80.85,41.92 76.79,41.92 76.54,41.67 69.11,41.67 65.85,44.94 54.77,44.94 50.7,49 42.72,49 41.96,48.24 40.69,48.24 39.55,47.1 33.45,47.1 31.42,45.07 28.52,45.07 27.25,43.8 21.16,43.8 18.15,40.79 18.15,38.84 19.69,37.31 19.69,31.42 20.98,30.12 23,30.12 23.13,29.99 23.13,28.74 23.25,28.62 23.43,28.62 23.54,28.72 v1(23.54,28.99)
  BOTTOM w0.089: JX4.22 80.81,42.57 80.52,42.86 80.29,42.86 v1(80.04,42.6)
IO_L02_34_JX4_P: length 89.8
  TOP w0.089: U1.T12 v1(24.34,28.99)
  L15_SIGNAL w0.089: v1(24.34,28.99) 24.08,28.99 23.93,29.14 23.93,30.01 23.81,30.13 23.35,30.13 23.1,30.38 21.09,30.38 19.94,31.53 19.94,37.41 18.4,38.95 18.4,40.69 21.26,43.54 27.36,43.54 28.63,44.81 31.53,44.81 33.56,46.84 39.65,46.84 40.8,47.99 42.07,47.99 42.83,48.75 50.6,48.75 54.66,44.69 65.74,44.69 69.01,41.42 76.65,41.42 76.89,41.66 80.96,41.66 81.32,42.02 81.32,42.78 80.78,43.31 v1(80.04,43.31)
  BOTTOM w0.089: v1(80.04,43.31) 80.28,43.07 80.51,43.07 80.81,43.37 JX4.20
IO_L02_35_RX_D1_N: length 39.7
  TOP w0.089: U17.K10 v1(68.4,32.89) ; U1.A20 v1(37.14,22.59)
  L3_SIGNAL w0.089: v1(68.4,32.89) 68.4,32.62 68.27,32.49 67.39,32.49 67.17,32.28 67.17,30.27 66.92,30.02 66.39,30.02 64.76,28.39 64.76,27.98 64.51,27.73 60.24,27.73 59.98,27.98 55.24,27.98 51.77,24.52 44.41,24.52 43.63,25.29 42.45,25.29 40.62,23.47 37.59,23.47 37.47,23.35 37.47,23.25 37.27,23.05 36.98,23.05 36.89,22.96 36.89,22.84 v1(37.14,22.59)
IO_L02_35_RX_D1_P: length 39.8
  TOP w0.089: U17.J11 v1(67.6,33.69) ; v1(36.34,23.39) U1.B19
  L3_SIGNAL w0.089: v1(67.6,33.69) 67.87,33.69 68,33.57 68,33.39 67.87,33.26 67.36,33.26 67.17,33.07 67.17,32.68 66.98,32.49 66.66,32.49 66.35,32.18 66.35,30.33 64.57,28.56 60.29,28.56 59.97,28.24 55.13,28.24 51.67,24.77 44.52,24.77 43.74,25.55 42.34,25.55 40.52,23.72 37,23.72 36.76,23.48 36.76,23.23 36.71,23.18 36.54,23.18 v1(36.34,23.39)
IO_L03_34_JX4_N: length 114.5
  TOP w0.089: U1.V13 v1(22.74,28.19)
  L15_SIGNAL w0.089: v1(22.74,28.19) 23.05,28.19 23.18,28.06 23.18,27.89 23.07,27.78 22.62,27.78 22.34,27.5 22.34,27.16 22.15,26.97 20.88,26.97 20.63,26.71 20.18,26.71 19.48,27.41 15.86,27.41 13.58,29.7 13.58,35.92 14.72,37.07 14.72,39.22 14.02,39.92 14.02,44.39 18.06,48.43 27.65,48.43 30.51,51.29 72.59,51.29 74.62,49.26 78.03,49.26 79.05,48.24 80.44,48.24 82.09,46.59 84.63,46.59 86.2,45.03 86.2,41.38 86.89,40.68 87.26,40.68 87.35,40.6 88.06,40.6 88.18,40.48 88.18,40.3 88.1,40.23 v1(87.69,40.23)
  BOTTOM w0.089: v1(87.69,40.23) 87.45,40.46 86.99,40.46 86.7,40.17 JX4.27
IO_L03_34_JX4_P: length 115.1
  TOP w0.089: R53.1 v1(87.69,40.94) ; U1.U13 23.59,28.24 v1(23.54,28.19)
  L15_SIGNAL w0.089: v1(23.54,28.19) 23.54,27.87 23.17,27.5 23.17,27.2 22.94,26.97 22.51,26.97 22.37,26.83 22.37,26.4 22.18,26.21 20.88,26.21 20.63,26.46 20.08,26.46 19.38,27.16 15.76,27.16 13.32,29.59 13.32,36.03 14.47,37.17 14.47,39.12 13.77,39.82 13.77,44.5 17.96,48.69 27.55,48.69 30.41,51.54 72.7,51.54 74.73,49.51 78.14,49.51 79.15,48.5 80.55,48.5 82.2,46.84 84.74,46.84 86.45,45.13 86.45,41.49 87,40.94 v1(87.69,40.94)
  BOTTOM w0.089: v1(87.69,40.94) 87.43,40.68 87,40.68 86.71,40.97 JX4.25
IO_L03_35_RX_D2_N: length 44.5
  TOP w0.089: U1.D18 v1(34.74,24.19) ; U17.K9 v1(68.4,32.09)
  L7_SIGNAL w0.089: v1(34.74,24.19) 35.06,24.19 35.4,23.85 35.55,23.85 35.87,23.53 35.87,23.38 36.2,23.05 36.35,23.05 36.67,22.73 36.67,22.58 37,22.25 37.09,22.25 37.13,22.21 39.77,22.21 39.82,22.16 40.18,22.16 40.38,21.95 41.94,21.95 42.29,22.3 42.57,22.3 42.66,22.21 42.99,22.21 43.09,22.3 43.37,22.3 43.46,22.21 44.59,22.21 44.69,22.3 44.97,22.3 45.06,22.21 46.31,22.21 46.52,22 46.8,22 47.01,22.21 47.79,22.21 47.89,22.3 48.17,22.3 48.26,22.21 48.59,22.21 48.69,22.3 48.97,22.3 49.14,22.12 51.41,22.12 55.42,26.14 55.42,27.79 56.06,28.43 57.22,28.43 58.24,29.45 59.11,29.45 59.74,30.08 59.74,32.49 59.99,32.74 59.99,32.96 60.26,33.23 67.77,33.23 68,33 68,32.49 v1(68.4,32.09)
IO_L03_35_RX_D2_P: length 44.5
  TOP w0.089: U1.E17 v1(33.94,24.99) ; U17.J10 v1(67.6,32.89)
  L7_SIGNAL w0.089: v1(67.6,32.89) 67.62,32.87 67.62,32.62 67.49,32.49 66.6,32.49 66.54,32.56 65.84,32.56 65.42,32.98 64.89,32.98 64.73,32.82 64.73,32.75 64.54,32.56 60.17,32.56 60,32.39 60,29.98 59.21,29.19 58.35,29.19 57.33,28.18 56.16,28.18 55.68,27.69 55.68,26.04 51.51,21.87 49.21,21.87 48.91,21.57 42.34,21.57 42.22,21.7 40.28,21.7 40.07,21.91 39.71,21.91 39.67,21.95 37.03,21.95 36.98,22 36.89,22 36.66,22.23 36.21,22.23 35.87,22.58 35.87,22.73 35.55,23.05 35.4,23.05 35.07,23.38 35.07,23.53 34.75,23.85 34.6,23.85 34.28,24.17 34.28,24.81 34.1,24.99 v1(33.94,24.99)
IO_L04_34_JX4_N: length 98.7
  TOP w0.089: U1.W13 v1(21.94,28.19)
  L15_SIGNAL w0.089: v1(84.28,41.2) 84.28,42.28 83.72,42.83 82.48,42.83 80.62,44.69 78.23,44.69 76.96,43.42 75.34,43.42 72.8,45.96 69.56,45.96 67.15,48.37 52.76,48.37 50.92,50.21 41.54,50.21 39.06,47.73 30.85,47.73 29.14,46.02 27.59,46.02 26.95,46.65 23.61,46.65 21.52,44.56 19.31,44.56 17.07,42.31 17.07,36.05 16.63,35.61 16.63,30.67 18.17,29.13 20.37,29.13 20.92,28.58 21.54,28.58 v1(21.94,28.19)
  BOTTOM w0.089: v1(84.28,41.2) 84.28,40.47 83.98,40.17 JX4.28
IO_L04_34_JX4_P: length 98.7
  TOP w0.089: U1.V12 v1(22.74,28.99)
  L15_SIGNAL w0.089: v1(83.57,41.2) 83.76,41.39 83.9,41.39 84.02,41.51 84.02,42.17 83.62,42.58 82.37,42.58 80.52,44.43 78.34,44.43 77.07,43.16 75.24,43.16 72.7,45.7 69.46,45.7 67.04,48.11 52.65,48.11 50.81,49.96 41.64,49.96 39.17,47.48 30.96,47.48 29.24,45.76 27.48,45.76 26.85,46.4 23.72,46.4 21.62,44.3 19.42,44.3 17.32,42.21 17.32,35.94 16.88,35.5 16.88,30.78 18.28,29.38 22.34,29.38 v1(22.74,28.99)
  BOTTOM w0.089: JX4.26 82.67,40.97 82.76,40.88 82.76,40.51 82.88,40.39 83.89,40.39 84.06,40.56 84.06,40.84 83.92,40.98 83.78,40.98 v1(83.57,41.2)
IO_L04_35_RX_D3_N: length 43.9
  TOP w0.089: U17.K8 v1(68.4,31.29) ; U1.D20 v1(34.74,22.59)
  L3_SIGNAL w0.089: v1(34.74,22.59) 34.74,22.32 34.85,22.2 35.06,22.2 35.18,22.32 35.33,22.32 35.49,22.16 35.49,21.97 35.76,21.7 38.26,21.7 38.89,22.33 40.59,22.33 41.09,21.83 42.09,21.83 42.29,21.63 43.37,21.63 43.56,21.83 44.49,21.83 44.69,21.63 48.97,21.63 49.16,21.83 56.86,21.83 59.15,24.11 62.49,24.11 63.17,24.79 63.17,25.89 63.43,26.14 64.52,26.14 64.73,26.35 64.73,26.79 65.7,27.76 66.14,27.76 66.33,27.95 66.33,28.39 66.48,28.55 66.92,28.55 67.13,28.75 67.13,29.22 67.36,29.45 67.72,29.45 68.22,29.94 68.67,29.94 68.76,30.03 68.76,31.6 68.63,31.73 68.51,31.73 68.38,31.6 68.38,31.31 v1(68.4,31.29)
IO_L04_35_RX_D3_P: length 43.9
  TOP w0.089: U17.J9 v1(67.6,32.09) ; U1.D19 v1(34.74,23.39)
  L3_SIGNAL w0.089: v1(67.6,32.09) 68.06,31.63 68.06,30.14 67.62,29.7 66.85,29.7 66.33,29.18 66.33,28.75 66.14,28.56 65.71,28.56 65.33,28.18 65.33,27.75 64.41,26.83 62.66,26.83 62.41,26.58 62.41,24.62 62.16,24.37 59.04,24.37 56.76,22.08 49.2,22.08 48.98,22.3 47.89,22.3 47.51,21.93 45.25,21.93 45.16,22.02 45.16,22.1 44.97,22.3 42.29,22.3 42.06,22.08 41.2,22.08 40.69,22.59 38.79,22.59 38.15,21.95 35.87,21.95 35.74,22.08 35.74,22.26 35.94,22.46 35.94,22.78 35.75,22.97 35.16,22.97 v1(34.74,23.39)
IO_L05_34_JX4_N: length 91.3
  TOP w0.089: U1.T15 v1(24.34,26.59)
  L3_SIGNAL w0.089: v1(24.34,26.59) 24.34,26.89 24.27,26.95 24.1,26.95 23.94,26.79 23.94,22.38 23.7,22.14 23.7,17.44 25.16,15.98 31.8,15.98 32.11,16.29 55.48,16.29 56.63,17.44 61.95,17.44 62.23,17.73 62.23,18.73 62.68,19.18 63.29,19.18 63.41,19.31 63.41,19.44 v1(63.62,19.64)
  L13_SIGNAL w0.089: v1(83.49,38.61) 83.68,38.42 83.82,38.42 83.95,38.3 83.95,35.97 82.07,34.09 78.11,34.09 77.08,33.06 77.08,27.1 71.17,21.19 71.17,19.49 70.86,19.18 63.93,19.18 63.84,19.27 63.84,19.41 v1(63.62,19.64)
  BOTTOM w0.089: v1(83.49,38.61) 83.85,38.26 84.25,38.26 84.44,38.07 84.93,38.07 85.22,37.77 JX4.33
IO_L05_34_JX4_P: length 91.2
  TOP w0.089: U1.T14 v1(24.34,27.39)
  L3_SIGNAL w0.089: v1(63.62,18.93) 62.79,18.93 62.49,18.63 62.49,17.62 62.05,17.19 56.74,17.19 55.58,16.03 32.21,16.03 31.91,15.73 25.06,15.73 23.45,17.34 23.45,22.14 23.14,22.45 23.14,26.8 23.33,26.99 23.79,26.99 24.01,27.22 v1(24.34,27.39)
  L13_SIGNAL w0.089: v1(84.2,38.61) 84.2,35.87 82.17,33.84 78.21,33.84 77.33,32.96 77.33,26.99 71.43,21.09 71.43,19.39 70.97,18.93 v1(63.62,18.93)
  BOTTOM w0.089: JX4.31 85.19,38.57 84.9,38.28 84.53,38.28 v1(84.2,38.61)
IO_L05_35_RX_D4_N: length 41.2
  TOP w0.089: U1.E19 v1(33.94,23.39) ; U17.K7 v1(68.4,30.49)
  L4_SIGNAL w0.089: v1(68.4,30.49) 67.96,30.06 67.51,30.06 66.78,29.32 65.58,29.32 64.99,28.72 64.99,26.84 64.73,26.59 64.73,26.33 64.52,26.12 64.19,26.12 63.96,25.89 63.96,24.78 63.14,23.96 44.15,23.96 43.3,24.81 40.03,24.81 39.27,24.05 37.58,24.05 37.26,23.73 34.22,23.73 33.94,23.45 v1(33.94,23.39)
IO_L05_35_RX_D4_P: length 41.1
  TOP w0.089: U1.E18 v1(33.94,24.19) ; U17.J8 v1(67.6,31.29)
  L4_SIGNAL w0.089: v1(33.94,24.19) 33.94,24.21 34.34,24.62 37.26,24.62 37.58,24.3 39.16,24.3 39.93,25.06 43.4,25.06 44.25,24.21 63.03,24.21 63.25,24.43 63.25,25.82 63.46,26.03 63.61,26.03 64.03,26.46 64.03,26.65 64.21,26.83 64.44,26.83 64.73,27.12 64.73,28.83 65.48,29.57 66.67,29.57 67.26,30.16 67.26,30.96 v1(67.6,31.29)
IO_L06_13_JX2_P: length 59.2
  TOP w0.127: U1.V5 v1(22.74,35.39)
  L4_SIGNAL w0.095: v1(38.03,9.51) 38.03,9.7 36.25,11.47 36.25,13.06 35.29,14.01 35.29,15.35 34.79,15.86 33.45,15.86 33.07,16.24 32.12,16.24 31.29,15.41 26.09,15.41 25.2,16.3 17.58,16.3 17.39,16.49 15.48,16.49 13.51,18.46 13.51,33 15.55,35.03 22.4,35.03 22.74,35.36 v1(22.74,35.39)
  BOTTOM w0.14: v1(38.03,9.51) 37.53,9.01 JX2.18
IO_L06_34_JX4_N: length 80.2
  TOP w0.089: U1.R14 v1(25.14,27.39)
  L3_SIGNAL w0.089: v1(25.14,27.39) 25.14,27.35 24.74,26.96 24.74,23.98 24.93,23.79 25.34,23.79 25.54,23.6 25.54,21.12 26.44,20.22 27.98,20.22 29.12,19.08 40.3,19.08 42.09,17.29 50.64,17.29 51.62,18.27 54.89,18.27 55.71,19.08 58.91,19.08 60.38,20.56 62.84,20.56 v1(63.04,20.35)
  L13_SIGNAL w0.089: v1(63.04,20.35) 63.25,20.56 65.08,20.56 66.28,21.76 70.52,21.76 71.3,22.55 71.3,25.91 72.23,26.84 74.14,26.84 75.74,28.45 75.74,35.29 78.07,37.62 78.25,37.62 v1(78.45,37.42)
  BOTTOM w0.089: JX4.34 80.79,37.77 80.5,38.06 79.54,38.06 79.12,37.65 78.69,37.65 v1(78.45,37.42)
IO_L06_34_JX4_P: length 80.2
  TOP w0.089: U1.P14 v1(25.94,27.39)
  L3_SIGNAL w0.089: v1(25.94,27.39) 25.54,26.99 25.54,23.98 25.71,23.81 26.14,23.81 26.34,23.61 26.34,22.33 26.19,22.18 25.93,22.18 25.8,22.04 25.8,21.23 26.55,20.47 28.09,20.47 29.22,19.34 40.4,19.34 42.19,17.55 50.53,17.55 51.51,18.52 54.79,18.52 55.6,19.34 58.8,19.34 60.28,20.81 62.79,20.81 v1(63.04,21.06)
  L13_SIGNAL w0.089: v1(78.45,38.13) 78.19,37.87 77.97,37.87 75.49,35.39 75.49,28.56 74.03,27.1 72.12,27.1 71.05,26.02 71.05,22.65 70.41,22.02 66.18,22.02 64.97,20.81 63.3,20.81 v1(63.04,21.06)
  BOTTOM w0.089: v1(78.45,38.13) 78.71,37.87 79.03,37.87 79.45,38.28 80.51,38.28 80.81,38.57 JX4.32
IO_L06_35_RX_D5_N: length 46.3
  TOP w0.089: v1(33.14,24.99) U1.F17 ; U17.J7 v1(67.6,30.49)
  L7_SIGNAL w0.089: v1(67.6,30.49) 67.18,30.08 65.82,30.08 65.56,29.83 63.28,29.83 63.02,29.57 62.35,29.57 62.14,29.36 61.86,29.36 61.64,29.57 60.48,29.57 57.96,27.05 57.96,25.02 54.77,21.83 53.27,21.83 51.61,20.17 50.15,20.17 50,20.03 47.89,20.03 47.74,20.17 45.14,20.17 44.99,20.03 43.09,20.03 42.94,20.17 42.19,20.17 41.56,19.54 39.55,19.54 38.03,21.06 36.37,21.06 35.87,21.57 33.6,21.57 32.8,22.37 32.8,24.51 32.69,24.62 32.69,24.87 32.82,25 33.12,25 v1(33.14,24.99)
IO_L06_35_RX_D5_P: length 46.2
  TOP w0.089: v1(33.14,25.79) U1.F16 ; U17.H8 v1(66.8,31.29)
  L7_SIGNAL w0.089: v1(66.8,31.29) 66.41,30.91 65.89,30.91 65.65,30.67 65.65,30.27 65.46,30.08 63.17,30.08 62.92,29.83 62.34,29.83 62.14,30.03 61.86,30.03 61.65,29.83 60.38,29.83 57.71,27.16 57.71,25.13 54.66,22.08 53.16,22.08 51.51,20.43 50.09,20.43 49.82,20.7 47.89,20.7 47.61,20.43 45.26,20.43 44.99,20.7 43.09,20.7 42.81,20.43 42.09,20.43 41.45,19.79 39.65,19.79 38.13,21.32 36.48,21.32 35.97,21.83 33.71,21.83 33.45,22.08 33.45,22.33 33.58,22.46 33.58,25.38 33.17,25.79 v1(33.14,25.79)
IO_L07_34_JX4_N: length 131.8
  TOP w0.089: U1.Y17 21.54,25.38 21.14,24.99 v1(21.14,24.99)
  L15_SIGNAL w0.089: v1(90.78,39.68) 91.37,40.27 91.37,45.96 90.35,46.97 90.35,49.51 84.82,55.04 41.64,55.04 40.63,54.02 40.63,52.75 40.12,52.24 34.89,52.24 34,53.13 30.66,53.13 27.87,50.34 25.62,50.34 24.67,51.29 16.75,51.29 12.56,47.1 12.56,29.25 16.18,25.64 19.5,25.64 20.14,24.99 v1(21.14,24.99)
  BOTTOM w0.089: JX4.37 86.74,36.17 87.03,36.46 88.72,36.46 89.61,37.36 89.61,38.52 v1(90.78,39.68)
IO_L07_34_JX4_P: length 131.9
  TOP w0.089: U1.Y16 v1(21.14,25.79)
  L15_SIGNAL w0.089: v1(21.14,25.79) 21.45,25.79 21.55,25.69 21.55,25.51 21.44,25.39 20.93,25.39 20.78,25.24 20.25,25.24 19.6,25.89 16.29,25.89 12.82,29.36 12.82,46.99 16.86,51.04 24.56,51.04 25.52,50.08 27.97,50.08 30.76,52.88 33.9,52.88 34.79,51.99 40.23,51.99 40.88,52.64 40.88,53.91 41.75,54.78 84.72,54.78 90.1,49.41 90.1,46.87 91.11,45.85 91.11,40.38 90.83,40.1 90.66,40.1 90.57,40.19 v1(90.28,40.19)
  BOTTOM w0.089: v1(90.28,40.19) 90.28,39.9 90.39,39.78 90.39,39.6 89.4,38.61 89.4,37.45 88.63,36.68 87.04,36.68 86.75,36.97 JX4.35
IO_L07_35_RX_FRAME_N: length 71.1
  TOP w0.089: U1.M20 v1(27.54,22.59) ; U17.G7 v1(66,30.49)
  L12_SIGNAL w0.089: v1(66,30.49) 65.97,30.46 65.71,30.46 65.58,30.33 65.58,29.95 65.71,29.83 66.22,29.83 66.82,29.23 67.03,29.23 70.14,29.23 70.33,29.03 70.33,29.01 71.68,27.67 71.68,20.8 70.72,19.84 68.4,19.84 65.93,17.38 57.3,17.38 54.97,15.04 52.86,15.04 52.27,14.46 43.25,14.46 41.73,12.94 37.75,12.94 37.56,13.12 37.56,14.52 36.73,15.35 35.97,15.35 34.91,16.41 34.71,16.41 34.51,16.61 34.51,16.81 33.43,17.89 30.79,17.89 28.12,20.56 28.12,20.91 27.45,21.58 27.45,22.05 27.61,22.21 27.74,22.21 27.99,22.46 27.99,22.72 28.12,22.85 28.12,23.1 27.99,23.22 27.87,23.22 27.48,22.84 27.48,22.64 v1(27.54,22.59)
IO_L07_35_RX_FRAME_P: length 71.1
  TOP w0.089: U17.G8 v1(66,31.29) ; U1.M19 v1(27.54,23.39)
  L12_SIGNAL w0.089: v1(27.54,23.39) 27.52,23.39 27.2,23.06 27.2,21.48 27.87,20.81 27.87,20.45 30.68,17.63 33.33,17.63 34.26,16.7 34.26,16.5 34.61,16.16 34.81,16.16 35.87,15.09 36.63,15.09 37.31,14.41 37.31,13.02 37.64,12.68 41.84,12.68 43.36,14.21 52.38,14.21 52.96,14.79 55.07,14.79 57.41,17.13 66.04,17.13 68.5,19.59 70.83,19.59 71.93,20.69 71.93,27.77 70.59,29.12 70.59,29.14 70.24,29.48 66.92,29.48 66.47,29.93 66.47,30.34 66.46,30.35 66.46,30.85 66.02,31.29 v1(66,31.29)
IO_L08_34_JX4_N: length 113.8
  TOP w0.089: U1.Y14 v1(21.14,27.39)
  L15_SIGNAL w0.089: v1(79.1,36.92) 79.26,36.76 79.72,36.3 80.29,36.3 80.82,36.83 80.82,38.46 82.27,39.91 84.76,39.91 85.42,40.57 85.42,42.84 84.49,43.77 82.73,43.77 79.53,46.97 73.97,46.97 73.08,47.86 73.08,49.77 72,50.84 31.55,50.84 28.63,47.92 21.41,47.92 19.67,46.18 17.32,46.18 15.29,44.16 15.29,29.13 15.93,28.49 19.82,28.49 20.79,27.53 v1(21.14,27.39)
  BOTTOM w0.089: JX4.38 79.85,36.17 v1(79.1,36.92)
IO_L08_34_JX4_P: length 113.7
  TOP w0.089: U1.W14 v1(21.94,27.39)
  L15_SIGNAL w0.089: v1(79.61,37.42) 79.79,37.24 79.79,37.06 79.64,36.91 79.64,36.73 79.82,36.56 80.19,36.56 80.57,36.94 80.57,38.57 82.17,40.16 84.66,40.16 85.17,40.68 85.17,42.73 84.38,43.52 82.63,43.52 79.43,46.72 73.86,46.72 72.82,47.76 72.82,49.66 71.89,50.59 31.65,50.59 28.73,47.67 21.52,47.67 19.77,45.93 17.42,45.93 15.55,44.05 15.55,29.23 16.03,28.75 19.93,28.75 20.89,27.78 21.81,27.78 21.94,27.65 v1(21.94,27.39)
  BOTTOM w0.089: JX4.36 80.74,36.97 80.16,36.39 79.94,36.39 79.6,36.73 79.6,36.87 79.79,37.06 79.79,37.24 v1(79.61,37.42)
IO_L08_35_FB_CLK_N: length 66.4
  TOP w0.089: U17.G10 v1(66,32.89) ; U1.M18 v1(27.54,24.19)
  L6_SIGNAL w0.089: v1(27.54,24.19) 27.87,24.19 28,24.06 28,23.93 28.15,23.78 28.65,23.78 28.78,23.65 28.78,20.91 29.77,19.92 29.77,18.4 31.42,16.75 31.42,14.61 32.36,13.67 33.59,13.67 34.39,12.87 34.39,12.07 35.56,10.9 51.29,10.9 57.61,17.23 63.76,17.23 65.33,18.8 65.33,32.23 v1(66,32.89)
IO_L08_35_FB_CLK_P: length 66.3
  TOP w0.089: U17.F10 v1(64.4,32.89) ; U1.M17 v1(27.54,24.99)
  L6_SIGNAL w0.089: v1(64.4,32.89) 65.08,32.21 65.08,18.9 63.65,17.48 57.51,17.48 51.18,11.16 35.66,11.16 34.65,12.17 34.65,12.97 33.69,13.93 32.46,13.93 31.68,14.71 31.68,16.85 30.02,18.5 30.02,20.03 29.03,21.02 29.03,24.12 28.58,24.58 27.94,24.58 v1(27.54,24.99)
IO_L09_34_JX4_N: length 89.2
  TOP w0.089: U1.U17 v1(23.54,24.99)
  L7_SIGNAL w0.089: v1(23.54,24.99) 23.86,24.99 24.32,24.52 24.47,24.52 24.8,24.2 24.8,24.05 25.12,23.72 25.27,23.72 25.6,23.4 25.6,22.33 25.69,22.24 25.69,22.06 25.33,21.7 25.33,19.31 27.74,16.89 27.74,16.26 28.14,15.86 35.51,15.86 36.4,14.97 38.79,14.97 39.93,13.82 50.73,13.82 51.23,13.32 58.32,13.32 58.83,13.82 62.16,13.82 62.79,13.19 65.03,13.19 69.37,17.53 69.37,17.99 72,20.62 72,21.89 73.59,23.48 77.71,23.48 80,25.76 84.19,25.76 85.46,27.03 85.46,32.62 87.11,34.27 87.69,34.27 87.78,34.18 87.78,34.04 v1(88.01,33.82)
  BOTTOM w0.089: JX4.43 86.7,33.77 86.99,34.06 87.76,34.06 v1(88.01,33.82)
IO_L09_34_JX4_P: length 89.3
  TOP w0.089: U1.T16 v1(24.34,25.79)
  L7_SIGNAL w0.089: v1(88,34.53) 87.01,34.53 85.21,32.73 85.21,27.14 84.08,26.02 79.89,26.02 77.61,23.73 73.48,23.73 71.74,21.99 71.74,20.72 69.11,18.09 69.11,17.63 64.92,13.44 62.9,13.44 62.26,14.08 58.73,14.08 58.22,13.57 51.34,13.57 50.83,14.08 40.04,14.08 38.89,15.22 36.5,15.22 35.61,16.11 28.25,16.11 27.99,16.36 27.99,17 25.58,19.41 25.58,21.59 25.94,21.96 25.94,22.06 26.4,22.52 26.4,23.4 26.07,23.72 25.92,23.72 25.6,24.05 25.6,24.2 25.27,24.52 25.12,24.52 24.8,24.85 24.8,25 24.34,25.46 v1(24.34,25.79)
  BOTTOM w0.089: v1(88.01,34.53) 87.76,34.28 86.99,34.28 86.7,34.57 JX4.41
IO_L09_35_TX_FRAME_N: length 64.9
  TOP w0.089: U17.H9 v1(66.8,32.09) ; U1.L20 v1(28.34,22.59)
  L7_SIGNAL w0.089: v1(66.8,32.09) 67.06,32.09 67.43,31.73 69.33,31.73 69.65,31.41 70.16,31.41 70.85,30.72 70.85,25.4 69.04,23.59 69.04,20.39 65.27,16.62 59.03,16.62 58.01,15.6 37.52,15.6 35.94,17.18 30.99,17.18 29.73,18.44 29.73,20.09 28.67,21.15 28.67,21.93 28.52,22.08 27.99,22.08 27.87,22.21 27.87,22.46 27.99,22.59 28.33,22.59 v1(28.34,22.59)
IO_L09_35_TX_FRAME_P: length 65
  TOP w0.089: U17.G9 v1(66,32.09) ; U1.L19 v1(28.34,23.39)
  L7_SIGNAL w0.089: v1(28.34,23.39) 28.92,22.8 28.92,21.26 29.98,20.2 29.98,18.55 31.09,17.43 36.05,17.43 37.62,15.86 57.91,15.86 58.93,16.87 65.16,16.87 68.79,20.5 68.79,23.69 70.6,25.51 70.6,30.61 70.05,31.16 69.65,31.16 69.39,30.91 67.43,30.91 67.17,31.16 67.17,31.54 67.04,31.67 66.42,31.67 v1(66,32.09)
IO_L10_34_JX4_N: length 116
  TOP w0.089: U1.W15 v1(21.94,26.59)
  L12_SIGNAL w0.089: v1(78.73,31.79) 78.54,31.6 78.54,31.35 78.67,31.22 79.05,31.22 79.49,31.67 79.49,33.57 81.08,35.16 85.84,35.16 86.29,34.72 86.29,23.79 82.6,20.11 82.6,14.94 81.56,13.9 78.87,13.9 76.38,11.41 58.07,11.41 57.18,10.52 47.37,10.52 45.98,9.13 42.93,9.13 41.79,7.98 38.51,7.98 37.72,8.77 35.02,8.77 31.7,12.09 31.7,12.66 30.79,13.57 28.88,13.57 27.61,14.84 23.57,14.84 22.15,16.26 22.15,20.32 21.77,20.7 21.77,22.21 21.52,22.46 21.52,26.14 21.94,26.56 v1(21.94,26.59)
  BOTTOM w0.089: JX4.44 80.79,33.77 80.5,34.06 79.3,34.06 78.5,33.27 78.5,32.02 v1(78.73,31.79)
IO_L10_34_JX4_P: length 116.2
  TOP w0.089: U1.V15 v1(22.74,26.59)
  L12_SIGNAL w0.089: v1(22.74,26.59) 22.55,26.78 22.4,26.78 22.28,26.65 22.28,26.02 22.4,25.89 22.4,22.53 22.02,22.15 22.02,20.81 22.4,20.43 22.4,16.36 23.67,15.09 27.72,15.09 28.99,13.82 30.89,13.82 31.95,12.76 31.95,12.2 35.13,9.02 37.83,9.02 38.61,8.24 41.68,8.24 42.83,9.38 45.87,9.38 47.27,10.78 57.08,10.78 57.96,11.67 76.27,11.67 78.76,14.15 81.46,14.15 82.35,15.04 82.35,20.22 86.03,23.9 86.03,34.61 85.74,34.91 81.18,34.91 79.74,33.47 79.74,31.56 79.15,30.97 78.56,30.97 78.28,31.25 78.28,31.55 v1(78.04,31.79)
  BOTTOM w0.089: v1(78.04,31.79) 78.28,32.04 78.28,33.36 79.21,34.28 80.49,34.28 80.78,34.57 JX4.42
IO_L10_35_ENABLE: length 54.8
  TOP w0.127: U1.K19 v1(29.94,23.39) ; U17.G6 v1(66,28.89)
  L7_SIGNAL w0.095: v1(66,28.89) 66.42,29.32 67.81,29.32 68,29.13 68,25.32 67.87,25.19 67.49,25.19 66.03,23.73 60,23.73 56.38,20.11 56.38,19.35 54.03,17 42.03,17 41.39,16.36 38.15,16.36 36.5,18.02 35.23,18.02 34.34,18.9 30.79,18.9 30.52,19.17 30.52,20.82 29.52,21.83 29.52,22.97 v1(29.94,23.39)
IO_L10_35_SYNC_IN: length 49.1
  TOP w0.127: U17.H5 v1(66.8,28.09) ; U1.J19 v1(30.74,23.39)
  L7_SIGNAL w0.095: v1(66.8,28.09) 67.24,27.66 67.24,25.44 65.93,24.14 59.9,24.14 55.93,20.17 55.93,19.41 53.9,17.38 40.82,17.38 40.25,16.81 38.09,16.81 36.03,18.86 35.4,18.86 34.98,19.29 32.22,19.29 31.28,20.23 31.28,20.82 30.28,21.83 30.28,22.97 30.7,23.39 v1(30.74,23.39)
IO_L11_35_EN_AGC: length 54.6
  TOP w0.127: U17.G5 v1(66,28.09) ; U1.L16 v1(28.34,25.79)
  L13_SIGNAL w0.095: v1(66,28.09) 64.74,26.83 63.37,26.83 63.17,27.03 63.17,29.7 62.72,30.15 62.66,30.15 62.46,30.35 62.46,30.51 62.14,30.83 60.38,30.83 59.73,31.48 58.47,31.48 57.46,32.49 56.19,32.49 55.68,31.99 53.77,31.99 52.76,30.97 52.76,30.58 51.93,29.75 51.93,24.04 49.17,21.28 49.17,21.02 48.97,20.83 48.71,20.83 48.59,20.7 43.09,20.7 43.06,20.68 41.45,20.68 41.2,20.94 39.55,20.94 38.03,22.46 38.03,23.1 37.27,23.85 36.99,23.85 36.8,24.05 36.8,24.32 36.5,24.62 29.77,24.62 28.6,25.79 v1(28.34,25.79)
IO_L11_35_TXNRX: length 54.5
  TOP w0.127: U1.L17 v1(28.34,24.99) ; U17.H4 v1(66.8,27.29)
  L13_SIGNAL w0.095: v1(66.8,27.29) 66.41,26.91 65.58,26.91 64.82,26.14 63.43,26.14 63.14,26.43 63.14,26.63 62.94,26.83 62.74,26.83 62.34,27.23 62.34,27.43 62.14,27.63 61.94,27.63 61.54,28.03 61.54,28.23 61.34,28.43 61.14,28.43 60.74,28.83 60.74,29.03 60.25,29.52 60.25,30.08 59.57,30.76 59.57,30.98 59.37,31.18 58.01,31.18 57.71,31.48 55.68,31.48 55.3,31.1 53.77,31.1 52.93,30.26 52.93,27.53 52.5,27.1 52.5,24.24 51.49,23.22 51.49,22.38 49.81,20.7 49.22,20.7 48.45,19.93 41.46,19.93 41.2,19.67 40.44,19.67 40.14,19.96 39.79,19.96 39.59,20.16 39.59,20.51 37.64,22.46 37.64,22.59 37.18,23.05 36.99,23.05 36.8,23.25 36.8,23.44 36.38,23.85 29.79,23.85 28.66,24.99 v1(28.34,24.99)
IO_L11_SRCC_13_JX2_N: length 47.4
  TOP w0.089: U1.V7 v1(22.74,33.79)
  L15_SIGNAL w0.089: v1(46.24,14.92) 46.24,14.38 45.91,14.05 42.55,14.05 41.38,15.22 35.58,15.22 34.45,14.09 32,14.09 31.42,14.67 31.42,19.88 29.33,21.97 29.33,31.67 29.2,31.79 25.05,31.79 24.8,32.05 24.8,32.32 24.5,32.62 24.16,32.62 23.93,32.85 23.93,33.14 23.67,33.4 23.43,33.4 23.04,33.79 v1(22.74,33.79)
  BOTTOM w0.089: JX2.37 45.53,11.73 45.24,12.02 45.24,13.09 45.99,13.84 45.99,14.67 v1(46.24,14.92)
IO_L11_SRCC_13_JX2_P: length 47.3
  TOP w0.089: v1(23.53,33.79) 23.93,33.39 U1.U7
  L15_SIGNAL w0.089: v1(45.52,14.92) 45.69,14.75 45.85,14.75 45.98,14.62 45.98,14.48 45.81,14.31 45.34,14.31 45.12,14.52 44.88,14.52 44.66,14.31 42.65,14.31 41.48,15.48 35.47,15.48 34.34,14.35 32.11,14.35 31.68,14.78 31.68,19.98 29.58,22.08 29.58,31.77 29.3,32.05 28.84,32.05 28.75,32.14 28.75,32.38 28.58,32.56 24.93,32.56 24.73,32.76 24.73,33.1 24.91,33.29 24.91,33.47 24.81,33.57 24.63,33.57 24.44,33.38 24.07,33.38 23.92,33.53 23.92,33.69 23.83,33.78 23.54,33.78 v1(23.53,33.79)
  BOTTOM w0.089: JX2.35 44.73,11.73 45.02,12.02 45.02,13.18 45.77,13.93 45.77,14.67 v1(45.52,14.92)
IO_L11_SRCC_34_JX4_N: length 94.1
  TOP w0.089: v1(23.54,26.59) U1.U15
  L12_SIGNAL w0.089: v1(84.38,32.24) 84.25,32.37 83.92,32.37 83.8,32.24 83.8,31.47 84.57,30.69 84.57,29.53 81.54,26.5 81.54,18.37 75.6,12.43 69.01,12.43 68,13.44 63.57,13.44 63.07,13.95 58.58,13.95 56.01,11.39 45.57,11.39 44.71,10.52 34.85,10.52 29.77,15.6 24.58,15.6 23.42,16.77 23.42,22.21 23.17,22.46 23.17,26.65 23.29,26.78 23.35,26.78 v1(23.54,26.59)
  BOTTOM w0.089: JX4.47 85.12,32.17 84.89,32.4 84.55,32.4 v1(84.38,32.24)
